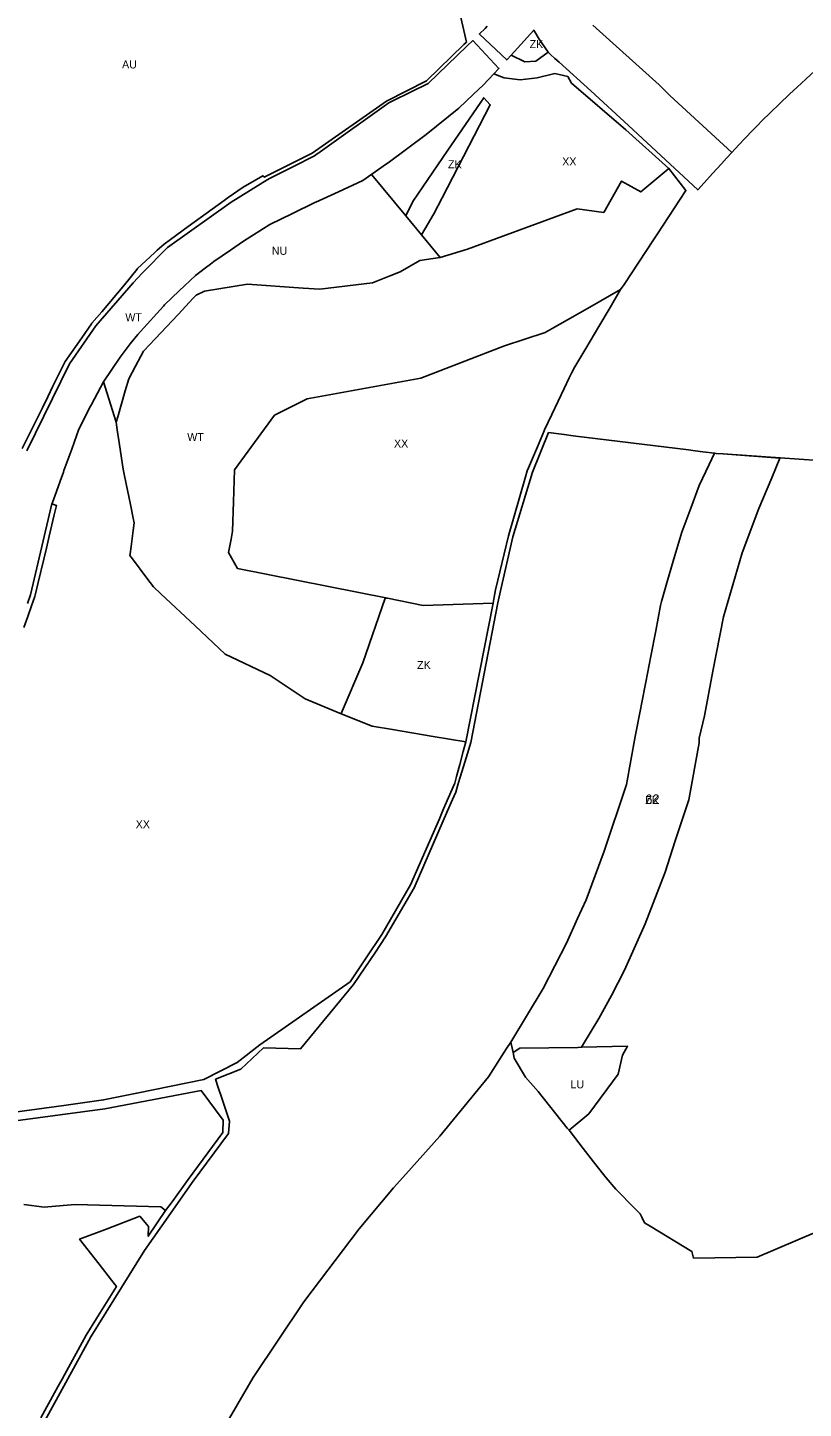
# Model space of a CAD drawing. Extents: x -537068 to -534056, y -1176840 to -1172401.
# Drawn here: x -535073 to -534588, y -1175951 to -1175088 of the extents above; entities that cross this region are included whole.
import ezdxf

# ---------------------------------------------------------------- set-up
doc = ezdxf.new("R2010")
doc.units = 0
for name, color, linetype in [('90550013', 7, 'Continuous'), ('90640013', 7, 'Continuous'), ('90710013', 7, 'Continuous'), ('90710023', 7, 'Continuous'), ('90730013', 7, 'Continuous'), ('90750013', 7, 'Continuous'), ('90770013', 7, 'Continuous'), ('ID_navrh', 7, 'Continuous')]:
    doc.layers.add(name, color=color, linetype=linetype)

msp = doc.modelspace()

# ---------------------------------------------------------------- linework, layer by layer
at = {"layer": '90550013'}
for points in [[(-534781.42, -1175116.91), (-534776.64, -1175118.75), (-534774.86, -1175119.44), (-534764.86, -1175120.57), (-534754.23, -1175119.31), (-534743.23, -1175116.69), (-534735.14, -1175118.41), (-534732.83, -1175122.62), (-534698.96, -1175151.8), (-534671.99, -1175175.95), (-534689.42, -1175190.63), (-534701.57, -1175183.88), (-534712.71, -1175203.47), (-534729.22, -1175201.14), (-534797.78, -1175226.37), (-534814.98, -1175231.54), (-534826.55, -1175217.54), (-534818.91, -1175204.32), (-534813.73, -1175194.33), (-534783.56, -1175136.2), (-534787.65, -1175131.83), (-534810.07, -1175164.62), (-534832, -1175196.71), (-534836.41, -1175205.6), (-534857.57, -1175179.98), (-534857.66, -1175179.64), (-534848.37, -1175173.18), (-534847.39, -1175172.45), (-534823.7, -1175154.79), (-534803.26, -1175138.27), (-534793.96, -1175129.55), (-534788.03, -1175123.99)], [(-534702.15, -1175251.67), (-534708.7, -1175262.76), (-534715.83, -1175274.83), (-534723.88, -1175288.45), (-534730.67, -1175299.94), (-534732.7, -1175303.37), (-534734.3, -1175306.78), (-534737.42, -1175313.42), (-534741.19, -1175321.42), (-534745.08, -1175329.69), (-534749.6, -1175339.29), (-534749.9, -1175339.92), (-534754.16, -1175349.99), (-534759.7, -1175363.09), (-534760.44, -1175364.83), (-534761.56, -1175368.72), (-534772.14, -1175405.55), (-534780.35, -1175439.37), (-534781.16, -1175443.84), (-534781.84, -1175447.55), (-534825.47, -1175449.02), (-534847.86, -1175444.57), (-534941.56, -1175425.95), (-534947.04, -1175415.96), (-534945.52, -1175407.54), (-534944.63, -1175402.62), (-534944.06, -1175384.28), (-534943.44, -1175364.36), (-534918.33, -1175330.08), (-534897.88, -1175319.97), (-534827.06, -1175307.09), (-534774.71, -1175286.87), (-534749.22, -1175278.45), (-534744.88, -1175275.98), (-534735.27, -1175270.51), (-534721.4, -1175262.62)]]:
    msp.add_lwpolyline(points, close=True, dxfattribs=at)
for points in [[(-535075.07, -1175462.83), (-535072.61, -1175456.03), (-535070.16, -1175449.26), (-535068.05, -1175443.45), (-535067.86, -1175442.64), (-535065.99, -1175434.65), (-535062.58, -1175420.14), (-535060.96, -1175413.24), (-535059.21, -1175405.79), (-535056.07, -1175392.43), (-535054.7, -1175386.57), (-535057.52, -1175385.55), (-535057.19, -1175384.65), (-535054.68, -1175377.74), (-535052.34, -1175371.3), (-535050.32, -1175365.73), (-535049.95, -1175364.72), (-535045.11, -1175351.39), (-535040.57, -1175338.89), (-535039.43, -1175336.59), (-535036.18, -1175330.08), (-535033.42, -1175324.55), (-535032.81, -1175323.44), (-535025.14, -1175309.36), (-535017.35, -1175334.54), (-535016.63, -1175339.31), (-535015.22, -1175348.68), (-535012.93, -1175363.83), (-535012.05, -1175368.1), (-535008.36, -1175386.06), (-535006.61, -1175394.55), (-535006.04, -1175397.34), (-535006.66, -1175402.16), (-535007.09, -1175405.52), (-535007.95, -1175412.19), (-535008.54, -1175416.73), (-535008.69, -1175417.9), (-535007.2, -1175419.88), (-534998.1, -1175431.98), (-534993.95, -1175437.5), (-534989.44, -1175441.72), (-534968, -1175461.79), (-534949.12, -1175479.46), (-534921.17, -1175492.83), (-534899.33, -1175507.44), (-534876.64, -1175516.69), (-534857.33, -1175524.56), (-534844.69, -1175526.66), (-534819.34, -1175530.87), (-534798.91, -1175534.27), (-534800.49, -1175540.25), (-534802.64, -1175548.39), (-534804.64, -1175555.94), (-534805.77, -1175560.19), (-534805.85, -1175560.51), (-534809.62, -1175569.15), (-534812.7, -1175576.21), (-534815.36, -1175582.32), (-534833.4, -1175623.66), (-534851.31, -1175654.61), (-534861.07, -1175669.23), (-534871.16, -1175684.32), (-534927.5, -1175723.52), (-534941.75, -1175734.73), (-534962.54, -1175745.2), (-535004.49, -1175753.79), (-535025.18, -1175758.03), (-535050.13, -1175761.47), (-535079.13, -1175765.46)], [(-535075.08, -1175823.28), (-535062.41, -1175825.11), (-535050.4, -1175823.98), (-535043.04, -1175823.29), (-534989.46, -1175824.91), (-534986.43, -1175827.21), (-534997.31, -1175843.24), (-534997.06, -1175837.16), (-535002.6, -1175830.73), (-535023.04, -1175838.49), (-535040.14, -1175844.98), (-535028.03, -1175860.61), (-535020.24, -1175870.67), (-535017.19, -1175874.61), (-535029.65, -1175894.7), (-535036.02, -1175904.98), (-535049.68, -1175929.91), (-535051.15, -1175932.6), (-535053.54, -1175936.95), (-535055.84, -1175941.16), (-535064.33, -1175956.65)]]:
    msp.add_lwpolyline(points, dxfattribs=at)
at = {"layer": '90640013'}
for points in [[(-534719.56, -1175086.43), (-534678.09, -1175123.81), (-534671.31, -1175130.46), (-534632.65, -1175165.96), (-534635.88, -1175169.51), (-534639.11, -1175173.05), (-534644.69, -1175179.18), (-534649.96, -1175184.96), (-534653.97, -1175189.37), (-534697.1, -1175149.18), (-534720.8, -1175127.43), (-534740.58, -1175109.61), (-534743.28, -1175107.18), (-534745.98, -1175104.75), (-534747.48, -1175103.4), (-534753.01, -1175095.21), (-534756.41, -1175089.48), (-534770.56, -1175105.2), (-534773.31, -1175108.17), (-534790.4, -1175091.99), (-534790.32, -1175091.91), (-534786.8, -1175088.49), (-534785.44, -1175087.07)], [(-535073.18, -1175352.43), (-535046.44, -1175297.98), (-535030.1, -1175274.28), (-535006.62, -1175247.42), (-535000.77, -1175241.14), (-534985.25, -1175225.31), (-534945.43, -1175197.06), (-534922.88, -1175183.02), (-534921.01, -1175182.07), (-534906.46, -1175174.67), (-534893.48, -1175168.07), (-534892.59, -1175167.44), (-534889.89, -1175165.51), (-534847.04, -1175134.87), (-534844.45, -1175133.62), (-534822.38, -1175122.93), (-534797.92, -1175099.3), (-534794.55, -1175096.02), (-534778.22, -1175113.45), (-534778.21, -1175113.45), (-534781.42, -1175116.91), (-534788.03, -1175123.99), (-534793.96, -1175129.55), (-534803.26, -1175138.27), (-534823.7, -1175154.79), (-534847.39, -1175172.45), (-534848.37, -1175173.18), (-534857.66, -1175179.64), (-534863.19, -1175183.49), (-534878.38, -1175190.51), (-534892.65, -1175197.11), (-534893.11, -1175197.32), (-534907.23, -1175204.22), (-534921.26, -1175211.07), (-534937.77, -1175221.49), (-534945.94, -1175227.05), (-534956.3, -1175234.1), (-534958.37, -1175235.69), (-534961.57, -1175238.15), (-534967.79, -1175242.94), (-534977.93, -1175252.51), (-534987.23, -1175261.29), (-534987.85, -1175261.98), (-535002.18, -1175277.78), (-535003.86, -1175279.64), (-535008.52, -1175285.66), (-535014.83, -1175293.8), (-535025.14, -1175309.36), (-535032.81, -1175323.44), (-535033.42, -1175324.55), (-535036.18, -1175330.08), (-535039.43, -1175336.59), (-535040.57, -1175338.89), (-535045.11, -1175351.39), (-535049.95, -1175364.72), (-535050.32, -1175365.73), (-535052.34, -1175371.3), (-535054.68, -1175377.74), (-535057.19, -1175384.65), (-535057.52, -1175385.55), (-535070.86, -1175442.43), (-535072.82, -1175447.85)], [(-535063.2, -1175960.77), (-535033.24, -1175906.1), (-534999.62, -1175852.1), (-534983.44, -1175829.08), (-534969.88, -1175809.65), (-534947.07, -1175779.02), (-534946.52, -1175771.33), (-534951.76, -1175755.6), (-534953.52, -1175750.32), (-534955.25, -1175745.12), (-534939.36, -1175738.75), (-534925.24, -1175725.42), (-534902.05, -1175726.08), (-534868.94, -1175685.87), (-534855.33, -1175665.63), (-534848.96, -1175656.17), (-534831.04, -1175625.41), (-534810.23, -1175577.44), (-534807.17, -1175570.39), (-534805.18, -1175565.8), (-534803.79, -1175561.2), (-534802.53, -1175557.01), (-534800.28, -1175549.58), (-534797.85, -1175541.56), (-534795.78, -1175534.7), (-534778.75, -1175447.45), (-534777.26, -1175439.82), (-534769.45, -1175406.16), (-534757.17, -1175365.82), (-534747.12, -1175341.05), (-534737.46, -1175342.25), (-534731.77, -1175342.96), (-534659.8, -1175351.9), (-534655.59, -1175352.42), (-534650.83, -1175353.01), (-534643.48, -1175353.92), (-534646.77, -1175360.91), (-534652.96, -1175374.04), (-534658.28, -1175388.31), (-534663.25, -1175401.65), (-534663.85, -1175403.25), (-534668.17, -1175417.92), (-534672.73, -1175433.39), (-534676.59, -1175446.48), (-534677.11, -1175449.15), (-534680.17, -1175464.82), (-534683.27, -1175480.7), (-534686.46, -1175497.02), (-534689.12, -1175510.64), (-534689.8, -1175514.09), (-534693.13, -1175530.98), (-534698.48, -1175560.95), (-534712.33, -1175602.64), (-534723.65, -1175632.94), (-534729.02, -1175644.76), (-534735.93, -1175659.99), (-534750.52, -1175688.37), (-534770.72, -1175721.95), (-534773.44, -1175725.87), (-534784.66, -1175743.55), (-534814.99, -1175780.73), (-534836.42, -1175804.33), (-534844.09, -1175812.91), (-534865.58, -1175838.65), (-534900.16, -1175884.16), (-534931.82, -1175931.47), (-534960.54, -1175980.81)], [(-535094.47, -1175772.94), (-535024.33, -1175763.57), (-534964.16, -1175752.21), (-534950.51, -1175770.73), (-534950.61, -1175778.33), (-534972.28, -1175807.68), (-534982.43, -1175821.7), (-534986.43, -1175827.21), (-534989.46, -1175824.91), (-535043.04, -1175823.29), (-535050.4, -1175823.98), (-535062.41, -1175825.11), (-535075.08, -1175823.28)]]:
    msp.add_lwpolyline(points, dxfattribs=at)
msp.add_lwpolyline([(-534702.15, -1175251.67), (-534721.4, -1175262.62), (-534735.27, -1175270.51), (-534744.88, -1175275.98), (-534749.22, -1175278.45), (-534774.71, -1175286.87), (-534827.06, -1175307.09), (-534897.88, -1175319.97), (-534918.33, -1175330.08), (-534943.44, -1175364.36), (-534944.06, -1175384.28), (-534944.63, -1175402.62), (-534945.52, -1175407.54), (-534947.04, -1175415.96), (-534941.56, -1175425.95), (-534847.86, -1175444.57), (-534849.31, -1175444.59), (-534863.29, -1175484.86), (-534876.75, -1175516.55), (-534876.64, -1175516.69), (-534899.33, -1175507.44), (-534921.17, -1175492.83), (-534949.12, -1175479.46), (-534968, -1175461.79), (-534989.44, -1175441.72), (-534993.95, -1175437.5), (-534998.1, -1175431.98), (-535007.2, -1175419.88), (-535008.69, -1175417.9), (-535008.54, -1175416.73), (-535007.95, -1175412.19), (-535007.09, -1175405.52), (-535006.66, -1175402.16), (-535006.04, -1175397.34), (-535006.61, -1175394.55), (-535008.36, -1175386.06), (-535012.05, -1175368.1), (-535012.93, -1175363.83), (-535015.22, -1175348.68), (-535016.63, -1175339.31), (-535017.35, -1175334.54), (-535016.34, -1175331.08), (-535011.66, -1175315), (-535009.44, -1175307.4), (-535005.24, -1175299.59), (-535000.2, -1175290.21), (-535000.07, -1175289.97), (-534993.04, -1175282.47), (-534978.67, -1175267.16), (-534969.21, -1175257.08), (-534967.42, -1175255.17), (-534962.17, -1175252.75), (-534935.34, -1175248.3), (-534900.58, -1175250.72), (-534890.06, -1175251.45), (-534857.14, -1175247.43), (-534846.81, -1175243.37), (-534839.9, -1175240.66), (-534827.68, -1175233.4), (-534815.07, -1175231.57), (-534814.98, -1175231.54), (-534797.78, -1175226.37), (-534729.22, -1175201.14), (-534712.71, -1175203.47), (-534701.57, -1175183.88), (-534689.42, -1175190.63), (-534671.99, -1175175.95), (-534661.36, -1175189.66), (-534679.16, -1175216.88), (-534681.52, -1175220.48), (-534699.91, -1175248.4)], close=True, dxfattribs=at)
at = {"layer": '90710013'}
for points in [[(-534747.48, -1175103.4), (-534755.11, -1175109), (-534761.9, -1175109.38), (-534770.56, -1175105.2), (-534756.41, -1175089.48), (-534753.01, -1175095.21)], [(-534826.55, -1175217.54), (-534836.41, -1175205.6), (-534832, -1175196.71), (-534810.07, -1175164.62), (-534787.65, -1175131.83), (-534783.56, -1175136.2), (-534813.73, -1175194.33), (-534818.91, -1175204.32)], [(-534876.64, -1175516.69), (-534876.75, -1175516.55), (-534863.29, -1175484.86), (-534849.31, -1175444.59), (-534847.86, -1175444.57), (-534825.47, -1175449.02), (-534781.84, -1175447.55), (-534798.91, -1175534.27), (-534819.34, -1175530.87), (-534844.69, -1175526.66), (-534857.33, -1175524.56)]]:
    msp.add_lwpolyline(points, close=True, dxfattribs=at)
at = {"layer": '90710023'}
msp.add_lwpolyline([(-534769.2, -1175728.4), (-534770.72, -1175721.95), (-534750.52, -1175688.37), (-534735.93, -1175659.99), (-534729.02, -1175644.76), (-534723.65, -1175632.94), (-534712.33, -1175602.64), (-534698.48, -1175560.95), (-534693.13, -1175530.98), (-534689.8, -1175514.09), (-534689.12, -1175510.64), (-534686.46, -1175497.02), (-534683.27, -1175480.7), (-534680.17, -1175464.82), (-534677.11, -1175449.15), (-534676.59, -1175446.48), (-534672.73, -1175433.39), (-534668.17, -1175417.92), (-534663.85, -1175403.25), (-534663.25, -1175401.65), (-534658.28, -1175388.31), (-534652.96, -1175374.04), (-534646.77, -1175360.91), (-534643.48, -1175353.92), (-534643.21, -1175353.95), (-534642.39, -1175354.01), (-534638.06, -1175354.31), (-534602.7, -1175357.11), (-534607.73, -1175369.2), (-534615.75, -1175388.41), (-534626.14, -1175416.23), (-534637.86, -1175456.11), (-534644.51, -1175490.19), (-534649.66, -1175518.02), (-534652.99, -1175531.91), (-534653.09, -1175534.8), (-534659.6, -1175570.59), (-534667.96, -1175596.16), (-534674.37, -1175615.81), (-534686.68, -1175647.91), (-534699.7, -1175676.93), (-534707.75, -1175692.79), (-534715.69, -1175707.17), (-534725.88, -1175724.1), (-534726.5, -1175725.15), (-534728.9, -1175725.2), (-534765, -1175725.6)], close=True, dxfattribs=at)
at = {"layer": '90730013'}
msp.add_lwpolyline([(-535025.14, -1175309.36), (-535014.83, -1175293.8), (-535008.52, -1175285.66), (-535003.86, -1175279.64), (-535002.18, -1175277.78), (-534987.85, -1175261.98), (-534987.23, -1175261.29), (-534977.93, -1175252.51), (-534967.79, -1175242.94), (-534961.57, -1175238.15), (-534958.37, -1175235.69), (-534956.3, -1175234.1), (-534945.94, -1175227.05), (-534937.77, -1175221.49), (-534921.26, -1175211.07), (-534907.23, -1175204.22), (-534893.11, -1175197.32), (-534892.65, -1175197.11), (-534878.38, -1175190.51), (-534863.19, -1175183.49), (-534857.66, -1175179.64), (-534857.57, -1175179.98), (-534836.41, -1175205.6), (-534826.55, -1175217.54), (-534814.98, -1175231.54), (-534815.07, -1175231.57), (-534827.68, -1175233.4), (-534839.9, -1175240.66), (-534846.81, -1175243.37), (-534857.14, -1175247.43), (-534890.06, -1175251.45), (-534900.58, -1175250.72), (-534935.34, -1175248.3), (-534962.17, -1175252.75), (-534967.42, -1175255.17), (-534969.21, -1175257.08), (-534978.67, -1175267.16), (-534993.04, -1175282.47), (-535000.07, -1175289.97), (-535000.2, -1175290.21), (-535005.24, -1175299.59), (-535009.44, -1175307.4), (-535011.66, -1175315), (-535016.34, -1175331.08), (-535017.35, -1175334.54)], close=True, dxfattribs=at)
at = {"layer": '90750013'}
for points in [[(-534806.93, -1175059.47), (-534798.45, -1175096.97), (-534800, -1175098.5), (-534823.52, -1175121.25), (-534848.38, -1175133.87), (-534894.94, -1175166.32), (-534923.98, -1175180.93), (-534924.68, -1175181.38), (-534925.65, -1175180.5), (-534937.89, -1175187.69), (-534947.44, -1175194.22), (-534949.86, -1175195.98), (-534972.25, -1175212.22), (-534983.42, -1175220.32), (-534987.36, -1175223.18), (-534991.63, -1175227.05), (-534993.31, -1175228.6), (-535003.94, -1175238.43), (-535004.26, -1175238.84), (-535012.03, -1175248.73), (-535026.36, -1175265.47), (-535032.45, -1175272.59), (-535032.81, -1175273.11), (-535038.82, -1175281.72), (-535049.22, -1175296.61), (-535056.8, -1175312.07), (-535060.09, -1175318.76), (-535063.39, -1175325.47), (-535070.02, -1175338.97), (-535075.96, -1175351.06)], [(-534545.11, -1175087.54), (-534545.66, -1175087.96), (-534555.11, -1175095.2), (-534560.85, -1175099.6), (-534565.67, -1175103.29), (-534571.09, -1175107.44), (-534580.87, -1175114.93), (-534586.43, -1175120.07), (-534591.89, -1175125.13), (-534596.67, -1175129.55), (-534602.87, -1175135.6), (-534608.46, -1175141.06), (-534613.82, -1175146.29), (-534616.62, -1175149.03), (-534618.99, -1175151.54), (-534624.87, -1175157.75), (-534630.7, -1175163.9), (-534632.65, -1175165.96), (-534671.31, -1175130.46), (-534678.09, -1175123.81), (-534719.56, -1175086.43)], [(-534567.5, -1175835.2), (-534616.7, -1175856.2), (-534656.5, -1175856.9), (-534657.6, -1175852.7), (-534683.7, -1175836.92), (-534687.2, -1175834.8), (-534688.94, -1175831.32), (-534690, -1175829.2), (-534694.65, -1175824.42), (-534703.42, -1175815.43), (-534705.1, -1175813.7), (-534711.11, -1175806.77), (-534712.9, -1175804.7), (-534719.09, -1175796.69), (-534725.5, -1175788.39), (-534734.3, -1175777), (-534721.9, -1175766.7), (-534703.6, -1175742), (-534700.9, -1175730.1), (-534697.8, -1175724.5), (-534726.5, -1175725.15), (-534725.88, -1175724.1), (-534715.69, -1175707.17), (-534707.75, -1175692.79), (-534699.7, -1175676.93), (-534686.68, -1175647.91), (-534674.37, -1175615.81), (-534667.96, -1175596.16), (-534659.6, -1175570.59), (-534653.09, -1175534.8), (-534652.99, -1175531.91), (-534649.66, -1175518.02), (-534644.51, -1175490.19), (-534637.86, -1175456.11), (-534626.14, -1175416.23), (-534615.75, -1175388.41), (-534607.73, -1175369.2), (-534602.7, -1175357.11), (-534638.06, -1175354.31), (-534554.99, -1175360.04)]]:
    msp.add_lwpolyline(points, dxfattribs=at)
at = {"layer": '90770013'}
msp.add_lwpolyline([(-534769.2, -1175728.4), (-534765, -1175725.6), (-534728.9, -1175725.2), (-534726.5, -1175725.15), (-534697.8, -1175724.5), (-534700.9, -1175730.1), (-534703.6, -1175742), (-534721.9, -1175766.7), (-534734.3, -1175777), (-534735.42, -1175775.61), (-534753.7, -1175752.8), (-534761.5, -1175743.9), (-534768.7, -1175731.9)], close=True, dxfattribs=at)

# ---------------------------------------------------------------- texts
at = {"layer": '90550013'}
for rotation, p in [(360, (-534738.64, -1175174.11)), (360, (-534843.74, -1175350.35)), (0, (-535005.12, -1175588.28))]:
    msp.add_text('XX', height=5, rotation=rotation, dxfattribs=at).set_placement(p)
at = {"layer": '90640013'}
for rotation, p in [(360, (-535011.63, -1175271.41)), (0, (-534972.9, -1175346.32))]:
    msp.add_text('WT', height=5, rotation=rotation, dxfattribs=at).set_placement(p)
at = {"layer": '90710013'}
for p in [(-534759.02, -1175100.8), (-534809.99, -1175175.81), (-534829.29, -1175488.74)]:
    msp.add_text('ZK', height=5, rotation=0, dxfattribs=at).set_placement(p)
at = {"layer": '90710023'}
msp.add_text('ZK', height=5, rotation=0, dxfattribs=at).set_placement((-534686.71, -1175573.14))
at = {"layer": '90730013'}
msp.add_text('NU', height=5, rotation=0, dxfattribs=at).set_placement((-534920.06, -1175229.92))
at = {"layer": '90750013'}
msp.add_text('AU', height=5, rotation=0, dxfattribs=at).set_placement((-535013.64, -1175113.47))
at = {"layer": '90770013'}
msp.add_text('LU', height=5, rotation=0, dxfattribs=at).set_placement((-534733.5, -1175750.79))
at = {"layer": 'ID_navrh'}
msp.add_text('62', height=6, rotation=360, dxfattribs=at).set_placement((-534686.71, -1175573.14))

doc.saveas('drawing.dxf')
